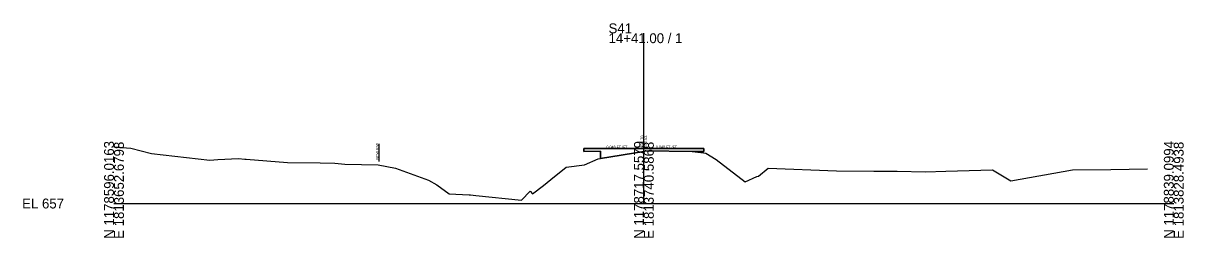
# Model space of a CAD drawing. Extents: x -241 to 10431, y -10 to 6540.
# Drawn here: x 2574.3 to 2902.8, y -9.7 to 51 of the extents above; entities that cross this region are included whole.
import ezdxf

# ---------------------------------------------------------------- set-up
doc = ezdxf.new("R2010")
doc.units = 0
for name, color, linetype in [('Default', 7, 'Continuous'), ('RD_GPK_XS_Cell', 7, 'Continuous'), ('RD_PD_RW', 7, 'Continuous'), ('RD_XS_Base', 7, 'Continuous'), ('RD_XS_ExGround', 7, 'Continuous'), ('RD_XS_Misc_Line', 7, 'Continuous'), ('RD_XS_Pave', 7, 'Continuous'), ('RD_XS_TX_Elev_EX', 7, 'Continuous'), ('RD_XS_TX_Slope', 7, 'Continuous')]:
    doc.layers.add(name, color=color, linetype=linetype)

msp = doc.modelspace()

# ---------------------------------------------------------------- linework, layer by layer
at = {"layer": 'Default'}
for q in [(2733, 15.52), (2767, 15.54)]:
    msp.add_line((2750, 15.53), q, dxfattribs=at)
at = {"layer": 'RD_GPK_XS_Cell'}
for p, q in [((2750, 0), (2750, 48.17)), ((2600, 0), (2750, 0)), ((2750, 0), (2900, 0))]:
    msp.add_line(p, q, dxfattribs=at)
at = {"layer": 'RD_PD_RW'}
msp.add_line((2675, 16.9), (2675, 11.9), dxfattribs=at)
at = {"layer": 'RD_XS_Base'}
for p, q in [((2733, 14.74), (2737.73, 14.84)), ((2737.73, 14.84), (2737.73, 12.78)), ((2763.64, 14.76), (2767, 14.76)), ((2763.64, 14.76), (2763.64, 14.76))]:
    msp.add_line(p, q, dxfattribs=at)
at = {"layer": 'RD_XS_ExGround'}
msp.add_lwpolyline([(2600, 16.06), (2604.81, 15.64), (2610.62, 14.13), (2627.16, 12.25), (2629.43, 12.41), (2635.22, 12.74), (2637.09, 12.59), (2637.45, 12.55), (2649.15, 11.62), (2658.4, 11.49), (2662.49, 11.45), (2665.31, 11.14), (2674.79, 10.91), (2679.68, 10.02), (2689.01, 6.59), (2691.41, 5.26), (2694.89, 2.77), (2700.52, 2.43), (2700.91, 2.42), (2702.44, 2.28), (2715.38, 0.97), (2717.8, 3.45), (2718.52, 2.75), (2721.55, 5.14), (2723.64, 6.79), (2728.04, 10.33), (2733.19, 10.97), (2737.08, 12.68), (2750, 14.7), (2750.56, 14.89), (2763.65, 14.76), (2766.9, 14.33), (2767.57, 14.26), (2770.47, 12.49), (2778.71, 6.12), (2782, 7.6), (2782.43, 7.71), (2785.15, 10.02), (2804.51, 9.28), (2815.06, 9.16), (2821.73, 9.14), (2829.68, 8.95), (2835.48, 9.17), (2848.71, 9.51), (2853.9, 6.43), (2871.32, 9.55), (2882.15, 9.65), (2892.57, 9.79)], dxfattribs=at)
at = {"layer": 'RD_XS_Misc_Line'}
for points in [[(2733, 14.74), (2733, 15.52), (2750, 15.53), (2767, 15.54), (2767, 14.76), (2763.64, 14.76), (2750.56, 14.89), (2750, 14.7), (2737.73, 12.78), (2737.73, 14.84)], [(2750.56, 14.89), (2763.64, 14.76), (2767, 14.76), (2767, 15.54), (2750, 15.53), (2733, 15.52), (2733, 14.74), (2737.73, 14.84), (2737.73, 12.78), (2750, 14.7)]]:
    msp.add_lwpolyline(points, close=True, dxfattribs=at)
at = {"layer": 'RD_XS_Pave'}
for p, q in [((2733, 14.74), (2733, 15.52)), ((2767, 14.76), (2767, 15.54))]:
    msp.add_line(p, q, dxfattribs=at)

# ---------------------------------------------------------------- texts
at = {"layer": 'Default'}
msp.add_text(' 672.53', height=0.8, rotation=90, dxfattribs=at).set_placement((2750.88, 15.53))
at = {"layer": 'RD_GPK_XS_Cell'}
for s, p in [('S41', (2740, 48.17)), ('14+41.00 / 1', (2740, 45.37)), ('EL 657', (2574, -1.4))]:
    msp.add_text(s, height=2.8, dxfattribs=at).set_placement(p)
for s, p in [('N 1178596.0163', (2600, -10)), ('E 1813652.6798', (2602.8, -10)), ('N 1178717.5579', (2750, -10)), ('E 1813740.5868', (2752.8, -10)), ('N 1178839.0994', (2900, -10)), ('E 1813828.4938', (2902.8, -10))]:
    msp.add_text(s, height=2.8, rotation=90, dxfattribs=at).set_placement(p)
at = {"layer": 'RD_PD_RW'}
msp.add_text('NEW R/W', height=0.75, rotation=90, dxfattribs=at).set_placement((2674.94, 12.43))
at = {"layer": 'RD_XS_TX_Elev_EX'}
msp.add_text('671.70', height=0.8, rotation=90, dxfattribs=at).set_placement((2749.89, 15.85))
at = {"layer": 'RD_XS_TX_Slope'}
for p in [(2739.4, 15.61), (2753.41, 15.62)]:
    msp.add_text('0.048 FT./FT.', height=0.75, rotation=0.0293, dxfattribs=at).set_placement(p)

doc.saveas('drawing.dxf')
